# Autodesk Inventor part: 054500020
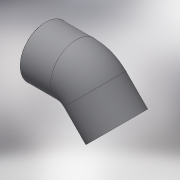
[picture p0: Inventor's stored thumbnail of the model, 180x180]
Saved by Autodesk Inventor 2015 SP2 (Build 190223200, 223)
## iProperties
Created: 2017-10
Part Number: 054500020
Material: Generic
Description: PLASSON 45° ELBOW CEMENT PVC 20
Document SubType Name: Modeling
Designer: KIM
Density: 1 g/cm^3
Appearance: Default
Author: KIM
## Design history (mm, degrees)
derived "054500.ipt"
feature "Solid1::054500.ipt"
tag "TaggingFeature1"
body "Solid1"
other parameters: "d1" = 26, "d5" = 18, "d7" = 0.2, "d9" = 26, "d13" = 135 deg, "d18" = 5, "d19" = 45 deg, "d21" = 16, "d22" = 0, "d24" = 135 deg, "d26" = 18, "d27" = 45 deg, "d28" = 21, "E_" = 26, "H_" = 35, "l_" = 16, "Z_" = 5
